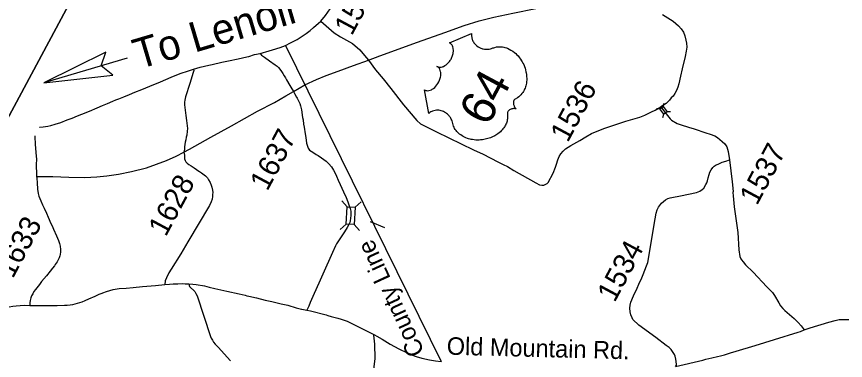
# Model space of a CAD drawing. Extents: x 1376167 to 1379209, y 761324 to 763997.
# Drawn here: x 1376443.7 to 1376608.1, y 762832.7 to 762900.9 of the extents above; entities that cross this region are included whole.
import ezdxf

# ---------------------------------------------------------------- set-up
doc = ezdxf.new("R2010")
doc.units = 0
for name, color, linetype in [('Default', 7, 'Continuous'), ('Old_Level_1', 7, 'Continuous'), ('Prop Terminator CELL', 7, 'Continuous'), ('Sheet Data Field CELL', 7, 'Continuous')]:
    doc.layers.add(name, color=color, linetype=linetype)

msp = doc.modelspace()

# ---------------------------------------------------------------- linework, layer by layer
at = {"layer": 'Default'}
for p, q in [((1376513.48, 762892.25), (1376514.88, 762890.36)), ((1376498.58, 762886.03), (1376500.84, 762887.38)), ((1376571.95, 762883.04), (1376572.15, 762883.71)), ((1376571.32, 762882.57), (1376570.62, 762882.57)), ((1376571.89, 762880.85), (1376572.09, 762881.52)), ((1376573.43, 762882), (1376572.74, 762882.01)), ((1376509.26, 762863.17), (1376508.21, 762864.35)), ((1376510.84, 762863.08), (1376512.01, 762864.13)), ((1376507.88, 762858.67), (1376509.06, 762859.72)), ((1376511.72, 762858.45), (1376510.67, 762859.63))]:
    msp.add_line(p, q, dxfattribs=at)
for points in [[(1376504, 762900), (1376504.98, 762901.08), (1376506.38, 762903.06), (1376507.51, 762904.85), (1376508.46, 762906.38), (1376508.94, 762907.17), (1376511.33, 762910.84), (1376512.6, 762912.83), (1376513.69, 762914.33), (1376514.02, 762914.72), (1376514.69, 762915.33), (1376515.38, 762915.87), (1376516.16, 762916.35), (1376516.96, 762916.71), (1376517.85, 762917.06)], [(1376513.48, 762892.25), (1376515.77, 762893.08), (1376523.24, 762895.79), (1376528.64, 762897.76), (1376532.48, 762899.12), (1376535.43, 762900.03), (1376538.39, 762900.76), (1376542.11, 762901.59), (1376546.68, 762902.48), (1376552.64, 762903.7), (1376557.79, 762904.81), (1376562.66, 762905.79), (1376567.02, 762906.76)], [(1376571.81, 762901.33), (1376573.94, 762899.95), (1376574.48, 762899.55), (1376575, 762899.08), (1376575.55, 762898.44), (1376575.96, 762897.78), (1376576.24, 762897.04), (1376576.46, 762896.2), (1376576.61, 762895.61), (1376576.64, 762894.82), (1376576.55, 762894.05), (1376576.3, 762893), (1376575.72, 762890.5), (1376575.41, 762889.06), (1376575.06, 762887.54), (1376574.86, 762886.87), (1376574.59, 762886.24), (1376574.25, 762885.62), (1376573.93, 762885.13), (1376573.57, 762884.76), (1376573.2, 762884.29), (1376572.53, 762883.68), (1376571.52, 762882.99)], [(1376497, 762895.15), (1376498.02, 762895.67), (1376499.32, 762896.35), (1376500.36, 762896.98), (1376501.15, 762897.55), (1376501.9, 762898.11), (1376502.61, 762898.71), (1376504, 762900)], [(1376504, 762900), (1376506.7, 762897.68), (1376507.96, 762896.88), (1376510.31, 762895.56), (1376511.76, 762894.31)], [(1376491.97, 762893.58), (1376493.78, 762894.08), (1376494.46, 762894.27), (1376495.98, 762894.75), (1376497, 762895.15)], [(1376497.02, 762895.14), (1376527.9, 762832.44)], [(1376511.76, 762894.31), (1376512.68, 762893.17), (1376513.48, 762892.25)], [(1376485.69, 762892.14), (1376487.65, 762892.5), (1376489.38, 762892.9), (1376489.77, 762892.98)], [(1376489.77, 762892.98), (1376490.89, 762893.34), (1376491.97, 762893.58)], [(1376491.97, 762893.58), (1376492.27, 762893.25), (1376492.88, 762892.81), (1376493.84, 762892.09), (1376494.97, 762891.3), (1376495.34, 762891.03), (1376495.61, 762890.79), (1376495.93, 762890.47), (1376496.25, 762890), (1376496.47, 762889.58), (1376496.74, 762889.16), (1376497, 762888.75), (1376497.21, 762888.36), (1376497.86, 762887.23), (1376498.05, 762886.92), (1376498.58, 762886.03)], [(1376478.79, 762890.45), (1376480.09, 762890.84), (1376480.96, 762891.08), (1376481.8, 762891.27), (1376482.46, 762891.41)], [(1376482.46, 762891.41), (1376484.4, 762891.88), (1376485.69, 762892.14)], [(1376500.84, 762887.38), (1376503.2, 762888.44), (1376505.12, 762889.23), (1376507.46, 762890.08), (1376510.52, 762891.2), (1376513.48, 762892.25)], [(1376473.72, 762888.64), (1376474.45, 762888.92), (1376476.32, 762889.64), (1376477.58, 762890.06), (1376478.79, 762890.45)], [(1376478.79, 762890.45), (1376478.81, 762890.21), (1376478.71, 762889.81), (1376478.02, 762887.59), (1376477.19, 762884.95), (1376477.04, 762884.33), (1376476.95, 762883.93), (1376476.95, 762883.41), (1376477.25, 762881.29), (1376477.39, 762880.28), (1376477.55, 762878.67), (1376477.54, 762878.19), (1376477.44, 762877.36), (1376477.33, 762876.94), (1376477.23, 762876.47), (1376477.12, 762876), (1376476.96, 762875.06), (1376476.95, 762874.67), (1376476.95, 762874.43), (1376476.87, 762874)], [(1376514.88, 762890.36), (1376516.37, 762888.57), (1376517.9, 762886.62), (1376520.41, 762883.38)], [(1376470.54, 762887.27), (1376471.75, 762887.78), (1376473.72, 762888.64)], [(1376466.05, 762885.43), (1376467.15, 762885.87), (1376468.53, 762886.45), (1376470.08, 762887.1)], [(1376470.08, 762887.1), (1376470.54, 762887.27)], [(1376459.64, 762882.78), (1376460.74, 762883.24), (1376461.68, 762883.67), (1376462.74, 762884.08), (1376463.37, 762884.35), (1376463.97, 762884.59)], [(1376463.97, 762884.59), (1376464.94, 762884.94), (1376466.05, 762885.43)], [(1376476.87, 762874), (1376477.96, 762874.61), (1376482.21, 762876.94), (1376486.29, 762879.19), (1376491.47, 762882.11), (1376494.84, 762883.82), (1376497.1, 762885.15), (1376498.58, 762886.03)], [(1376498.58, 762886.03), (1376498.83, 762885.63), (1376499.19, 762884.92), (1376499.31, 762884.68), (1376499.84, 762883.64), (1376499.99, 762883.16), (1376500.17, 762882.38), (1376500.41, 762880.9), (1376500.5, 762880.42), (1376500.6, 762879.58), (1376500.73, 762878.94), (1376500.94, 762877.61), (1376501.04, 762876.91), (1376501.19, 762875.81), (1376501.29, 762875.38), (1376501.49, 762874.79), (1376501.76, 762874.42), (1376502.11, 762874.16), (1376502.42, 762873.98), (1376503.13, 762873.56), (1376503.5, 762873.3), (1376504.17, 762872.86), (1376505.12, 762872.19), (1376505.64, 762871.67), (1376506.12, 762871.07), (1376506.53, 762870.42), (1376506.8, 762869.94), (1376507.11, 762869.21), (1376507.5, 762868.45), (1376507.87, 762867.61), (1376508.21, 762866.88), (1376508.56, 762866.13), (1376509.03, 762865.02), (1376509.36, 762864.12), (1376509.64, 762863.33), (1376509.84, 762862.8), (1376509.97, 762862.26), (1376509.99, 762861.95), (1376509.98, 762861.42)], [(1376455.78, 762881.21), (1376456.58, 762881.51), (1376458.11, 762882.15), (1376459.64, 762882.78)], [(1376520.41, 762883.38), (1376523.08, 762880.25), (1376523.84, 762879.62), (1376525.38, 762878.8), (1376526.97, 762878.02), (1376534.32, 762874.47), (1376536.21, 762873.57), (1376539.18, 762872.07), (1376540.2, 762871.53), (1376541.04, 762871.12), (1376542.34, 762870.37), (1376546.7, 762867.9), (1376547.45, 762867.52), (1376547.85, 762867.44), (1376548.25, 762867.47), (1376548.53, 762867.58), (1376548.91, 762867.75), (1376549.13, 762867.96), (1376550.14, 762869.83), (1376550.61, 762871), (1376550.77, 762871.62), (1376551.03, 762872.46), (1376551.33, 762873.14), (1376551.63, 762873.64), (1376552.09, 762874.21), (1376552.56, 762874.65), (1376553.66, 762875.31), (1376555.4, 762876.33), (1376556.62, 762877.06), (1376557.72, 762877.7), (1376560.17, 762878.69), (1376564.57, 762880.13), (1376567.34, 762880.91), (1376568.34, 762881.35), (1376569.62, 762882), (1376570.37, 762882.35), (1376571.52, 762882.99)], [(1376571.52, 762882.99), (1376571.83, 762882.53), (1376573.06, 762880.91), (1376573.35, 762880.59), (1376573.62, 762880.35), (1376574.76, 762879.69), (1376575.53, 762879.42), (1376576.96, 762878.98), (1376578.08, 762878.61), (1376580.45, 762877.82), (1376581.26, 762877.57), (1376582.2, 762877.2), (1376582.73, 762876.89), (1376583.23, 762876.51), (1376583.69, 762876.11), (1376584.16, 762875.62), (1376584.6, 762875.02), (1376584.86, 762874.12), (1376585.11, 762872.44)], [(1376448.21, 762878.95), (1376448.26, 762878.95), (1376448.96, 762879.04), (1376449.87, 762879.18), (1376450.48, 762879.31), (1376451.35, 762879.52), (1376452.46, 762879.89), (1376453.7, 762880.39), (1376454.68, 762880.76), (1376455.78, 762881.21)], [(1376447.27, 762877.2), (1376447.29, 762877.01), (1376447.38, 762875.56), (1376447.5, 762873.93), (1376447.59, 762872.52), (1376447.57, 762871.61), (1376447.57, 762870.78), (1376447.59, 762870.27), (1376447.65, 762869.18)], [(1376447.65, 762869.18), (1376450.89, 762869.14), (1376454.03, 762869.05), (1376457.23, 762868.98), (1376459.62, 762869.07), (1376461.55, 762869.3), (1376463.92, 762869.65), (1376466.49, 762870.13), (1376469.41, 762870.87), (1376473.43, 762872.34), (1376475.35, 762873.18), (1376476.87, 762874)], [(1376476.87, 762874), (1376476.95, 762873.4), (1376476.99, 762872.68), (1376477.11, 762872.37), (1376477.27, 762872.06), (1376477.49, 762871.81), (1376477.86, 762871.53), (1376478.29, 762871.25), (1376478.87, 762870.86), (1376479.82, 762870.23), (1376479.95, 762870.13), (1376480.35, 762869.86), (1376481.14, 762869.3), (1376481.52, 762868.89), (1376481.76, 762868.53), (1376482.09, 762868), (1376482.3, 762867.46), (1376482.42, 762867.05), (1376482.53, 762866.48), (1376482.59, 762865.98), (1376482.57, 762865.59), (1376482.57, 762865.22), (1376482.46, 762864.66), (1376482.29, 762864.13), (1376481.94, 762863.38), (1376477.62, 762856.23), (1376476.23, 762853.85), (1376474.35, 762850.75), (1376473.87, 762850.02), (1376473.39, 762849.09), (1376473.15, 762848.45), (1376473.1, 762847.75)], [(1376567.7, 762849.03), (1376568.02, 762849.74), (1376568.67, 762851.41), (1376568.93, 762852.12), (1376570.07, 762858.78), (1376570.14, 762859.67), (1376570.36, 762860.74), (1376570.54, 762861.9), (1376570.75, 762862.57), (1376571.01, 762863.06), (1376571.21, 762863.35), (1376571.64, 762863.9), (1376572.44, 762864.52), (1376572.88, 762864.77), (1376573.34, 762864.92), (1376573.7, 762865.03), (1376575.41, 762865.35), (1376578.56, 762866), (1376579.21, 762866.28), (1376579.68, 762866.57), (1376580, 762866.86), (1376580.45, 762867.55), (1376580.62, 762867.91), (1376580.76, 762868.31), (1376580.86, 762868.88), (1376581.06, 762869.57), (1376581.19, 762870), (1376581.48, 762870.52), (1376581.8, 762870.92), (1376582, 762871.15), (1376582.06, 762871.24), (1376582.47, 762871.49), (1376582.89, 762871.64), (1376583.69, 762871.99), (1376584.38, 762872.21), (1376585.11, 762872.44)], [(1376585.11, 762872.44), (1376585.64, 762868.12), (1376585.82, 762866.17), (1376585.8, 762866.01), (1376585.85, 762865.33), (1376586.03, 762863.16), (1376586.74, 762858.04), (1376586.98, 762854.59), (1376587.16, 762853.28), (1376587.36, 762852.82), (1376587.49, 762852.63), (1376587.82, 762852.21), (1376588.3, 762851.63), (1376589.78, 762850.19), (1376592.51, 762847.29), (1376592.85, 762846.93), (1376593.64, 762846.16), (1376594.07, 762845.53), (1376594.9, 762844.12), (1376595.23, 762843.5), (1376595.68, 762843), (1376596.09, 762842.58), (1376596.54, 762842.16), (1376597.03, 762841.78), (1376597.94, 762840.98), (1376598.76, 762840.19), (1376599.32, 762839.56), (1376599.9, 762838.75)], [(1376447.65, 762869.18), (1376447.68, 762868.81), (1376447.76, 762867.9), (1376447.82, 762866.68), (1376447.93, 762865.8), (1376448.08, 762865.26), (1376448.46, 762864.31), (1376448.79, 762863.57), (1376449.16, 762862.85), (1376449.58, 762861.86), (1376449.95, 762861.09), (1376450.47, 762859.84), (1376450.71, 762859.35), (1376451.01, 762858.73), (1376451.59, 762857.37), (1376451.97, 762856.49), (1376452.18, 762855.85), (1376452.31, 762855.37), (1376452.37, 762854.71), (1376452.37, 762854.22), (1376452.32, 762853.72), (1376452.25, 762853.42), (1376452.13, 762853), (1376451.69, 762852.22), (1376451.32, 762851.72), (1376451.18, 762851.45), (1376450.81, 762851), (1376450.3, 762850.35), (1376449.57, 762849.44), (1376448.64, 762848.31), (1376448.18, 762847.73), (1376447.44, 762846.77), (1376447.12, 762846.34), (1376446.86, 762845.89), (1376446.64, 762845.48), (1376446.5, 762845.1), (1376446.36, 762844.59), (1376446.29, 762844.07), (1376446.28, 762843.59)], [(1376509.98, 762861.42), (1376509.92, 762860.88), (1376509.86, 762860.35), (1376509.76, 762860.04), (1376509.57, 762859.62), (1376509.28, 762859.06), (1376508.7, 762858.2), (1376508.18, 762857.39), (1376507.91, 762857.01), (1376507.16, 762855.79), (1376506.96, 762855.44), (1376506.36, 762854.07), (1376504.44, 762849.76), (1376503.91, 762848.57), (1376502.47, 762845.34), (1376501.94, 762844.17), (1376501.62, 762843.42), (1376501.38, 762842.94), (1376501.27, 762842.63)], [(1376516.71, 762858.97), (1376513.92, 762860.14)], [(1376574.39, 762831.48), (1376574.57, 762831.71), (1376574.61, 762831.92), (1376574.49, 762832.91), (1376574.36, 762833.5), (1376574.22, 762833.85), (1376573.84, 762834.44), (1376573.53, 762834.81), (1376573.14, 762835.23), (1376572.52, 762835.66), (1376570.5, 762837.21), (1376567.13, 762839.67), (1376565.96, 762840.81), (1376565.78, 762841.11), (1376565.53, 762841.7), (1376565.39, 762842.29), (1376565.36, 762843.02), (1376565.39, 762843.64), (1376565.55, 762844.22), (1376566.09, 762845.52), (1376566.77, 762847.02), (1376567.16, 762847.79), (1376567.7, 762849.03)], [(1376446.28, 762843.59), (1376447.79, 762843.59), (1376449.44, 762843.56), (1376450.57, 762843.54), (1376451.75, 762843.58), (1376453.19, 762843.64), (1376453.73, 762843.63), (1376454.32, 762843.68), (1376454.81, 762843.76), (1376455.32, 762843.87), (1376456.71, 762844.33), (1376457.26, 762844.56), (1376458.01, 762844.89), (1376459.23, 762845.43), (1376459.27, 762845.44), (1376460.03, 762845.79), (1376460.65, 762846.02), (1376460.77, 762846.07), (1376461.5, 762846.38), (1376462.82, 762846.73)], [(1376462.82, 762846.73), (1376464.02, 762846.92), (1376465.42, 762846.98), (1376466.83, 762847.14), (1376468.66, 762847.32), (1376471.25, 762847.57), (1376473.1, 762847.75)], [(1376473.1, 762847.75), (1376474, 762847.83), (1376474.76, 762847.89), (1376475.65, 762847.9), (1376476.55, 762847.93), (1376477.13, 762847.9), (1376477.87, 762847.88)], [(1376477.87, 762847.88), (1376477.92, 762847.53), (1376477.99, 762847.36), (1376478.14, 762847.15), (1376478.83, 762846.55), (1376479.02, 762846.34), (1376479.26, 762845.98), (1376479.49, 762845.47), (1376482.12, 762837.43), (1376482.28, 762837.07), (1376482.52, 762836.68), (1376482.76, 762836.32), (1376483.08, 762835.92), (1376483.67, 762835.3), (1376486.09, 762832.57)], [(1376477.87, 762847.88), (1376478.62, 762847.81), (1376479.32, 762847.72), (1376480.92, 762847.48), (1376481.88, 762847.24), (1376483.03, 762846.92), (1376485.36, 762846.43), (1376487.81, 762845.89), (1376489, 762845.59), (1376489.36, 762845.49), (1376489.74, 762845.39), (1376491.25, 762845.06), (1376493.01, 762844.63), (1376494.32, 762844.37), (1376496.18, 762843.92), (1376497.47, 762843.61), (1376499.11, 762843.13), (1376500.22, 762842.85), (1376500.28, 762842.83), (1376501.27, 762842.63)], [(1376428.65, 762842.47), (1376429.73, 762842.51), (1376431.08, 762842.55), (1376432.73, 762842.67), (1376433.63, 762842.64), (1376436.24, 762842.87), (1376437.65, 762842.9), (1376439.73, 762842.96), (1376441.45, 762843.2), (1376442.95, 762843.46), (1376443.59, 762843.53), (1376444.38, 762843.56), (1376445.29, 762843.61), (1376446.28, 762843.59)], [(1376501.27, 762842.63), (1376502.01, 762842.48), (1376505.08, 762841.7), (1376505.4, 762841.61), (1376506.08, 762841.41), (1376507.4, 762841.05), (1376508.05, 762840.87), (1376508.65, 762840.67), (1376509.25, 762840.46), (1376510.47, 762839.87), (1376512.2, 762839), (1376513.64, 762838.25), (1376514.65, 762837.73)], [(1376599.9, 762838.75), (1376601.09, 762839.11), (1376604.8, 762840.25), (1376606.05, 762840.61), (1376606.9, 762840.79), (1376607.53, 762840.82), (1376608.79, 762840.77)], [(1376574.39, 762831.48), (1376579.85, 762832.75), (1376580.41, 762832.9), (1376581.64, 762833.17), (1376582.76, 762833.45), (1376583.31, 762833.6), (1376584.11, 762833.81), (1376585.32, 762834.18), (1376586.42, 762834.49), (1376590.21, 762835.65), (1376594.03, 762836.84), (1376598.72, 762838.28), (1376599.2, 762838.44), (1376599.9, 762838.75)], [(1376514.5, 762837.69), (1376514.66, 762835.92), (1376514.73, 762833.03), (1376514.55, 762831.4), (1376514.4, 762829.63), (1376514.26, 762826.49), (1376514.63, 762822.34)], [(1376514.65, 762837.73), (1376515.16, 762837.46), (1376516.17, 762836.91), (1376517.77, 762835.88), (1376519.52, 762834.96), (1376520.06, 762834.7), (1376521.21, 762834.17), (1376522.02, 762833.77), (1376522.95, 762833.46), (1376524.07, 762833.11)], [(1376524.07, 762833.11), (1376525.61, 762832.77), (1376526.77, 762832.56), (1376527.9, 762832.44)]]:
    msp.add_lwpolyline(points, dxfattribs=at)
for points in [[(1376524.58, 762886.33), (1376524.72, 762886.27), (1376524.89, 762886.22), (1376524.99, 762886.2), (1376525.19, 762886.19), (1376525.44, 762886.21), (1376525.72, 762886.28), (1376525.98, 762886.39), (1376526.14, 762886.48), (1376526.38, 762886.64), (1376526.62, 762886.83), (1376526.85, 762887.07), (1376527.06, 762887.33), (1376527.27, 762887.62), (1376527.44, 762887.93), (1376527.59, 762888.28), (1376527.72, 762888.69), (1376527.77, 762888.89), (1376527.81, 762889.11), (1376527.83, 762889.33), (1376527.83, 762889.58), (1376527.81, 762889.79), (1376527.79, 762889.96), (1376527.71, 762890.22), (1376527.62, 762890.45), (1376527.55, 762890.56), (1376527.49, 762890.66), (1376527.33, 762890.84), (1376527.25, 762890.9), (1376527.08, 762891.01), (1376527.23, 762890.94), (1376527.34, 762890.91), (1376527.44, 762890.88), (1376527.56, 762890.87), (1376527.74, 762890.86), (1376527.89, 762890.88), (1376528.14, 762890.93), (1376528.28, 762890.98), (1376528.39, 762891.02), (1376528.66, 762891.16), (1376528.93, 762891.35), (1376529.06, 762891.45), (1376529.17, 762891.56), (1376529.31, 762891.7), (1376529.44, 762891.84), (1376529.56, 762892), (1376529.68, 762892.16), (1376529.79, 762892.33), (1376529.87, 762892.47), (1376529.97, 762892.65), (1376530.04, 762892.82), (1376530.12, 762893), (1376530.18, 762893.2), (1376530.23, 762893.37), (1376530.28, 762893.59), (1376530.32, 762893.8), (1376530.33, 762893.99), (1376530.33, 762894.25), (1376530.32, 762894.47), (1376530.29, 762894.64), (1376530.23, 762894.86), (1376530.15, 762895.08), (1376530.08, 762895.22), (1376529.99, 762895.34), (1376529.89, 762895.45), (1376529.78, 762895.56), (1376529.67, 762895.63), (1376529.58, 762895.69), (1376533.93, 762897.56), (1376533.92, 762897.47), (1376533.91, 762897.24), (1376533.92, 762897.06), (1376533.96, 762896.75), (1376533.99, 762896.6), (1376534.03, 762896.46), (1376534.08, 762896.32), (1376534.13, 762896.19), (1376534.21, 762896.03), (1376534.3, 762895.87), (1376534.4, 762895.71), (1376534.49, 762895.58), (1376534.7, 762895.34), (1376534.84, 762895.21), (1376534.96, 762895.1), (1376535.23, 762894.9), (1376535.37, 762894.82), (1376535.5, 762894.75), (1376535.65, 762894.68), (1376535.8, 762894.62), (1376535.96, 762894.56), (1376536.1, 762894.52), (1376536.27, 762894.47), (1376536.49, 762894.44), (1376536.7, 762894.41), (1376537.06, 762894.41), (1376537.46, 762894.45), (1376537.69, 762894.5), (1376537.9, 762894.56), (1376538.18, 762894.67), (1376538.34, 762894.72), (1376538.53, 762894.78), (1376538.88, 762894.86), (1376539.03, 762894.88), (1376539.2, 762894.9), (1376539.37, 762894.91), (1376539.56, 762894.91), (1376539.71, 762894.91), (1376540.05, 762894.87), (1376540.37, 762894.81), (1376540.53, 762894.77), (1376540.88, 762894.66), (1376541.06, 762894.6), (1376541.38, 762894.46), (1376541.76, 762894.25), (1376542.1, 762894.03), (1376542.49, 762893.74), (1376542.71, 762893.55), (1376542.95, 762893.31), (1376543.16, 762893.09), (1376543.45, 762892.74), (1376543.65, 762892.46), (1376543.88, 762892.12), (1376544.01, 762891.9), (1376544.14, 762891.66), (1376544.28, 762891.36), (1376544.42, 762891.02), (1376544.56, 762890.64), (1376544.65, 762890.34), (1376544.74, 762889.96), (1376544.79, 762889.74), (1376544.83, 762889.43), (1376544.87, 762889.02), (1376544.89, 762888.63), (1376544.88, 762888.31), (1376544.86, 762888.04), (1376544.81, 762887.69), (1376544.68, 762887.13), (1376544.63, 762886.94), (1376544.55, 762886.71), (1376544.46, 762886.51), (1376544.37, 762886.31), (1376544.24, 762886.06), (1376544.08, 762885.82), (1376543.92, 762885.6), (1376543.73, 762885.37), (1376543.51, 762885.16), (1376543.3, 762884.97), (1376543.05, 762884.79), (1376542.58, 762884.53), (1376542.45, 762884.44), (1376542.4, 762884.39), (1376542.31, 762884.23), (1376542.26, 762884.07), (1376542.24, 762883.89), (1376542.24, 762883.77), (1376542.26, 762883.61), (1376542.28, 762883.48), (1376542.33, 762883.31), (1376542.37, 762883.18), (1376542.41, 762883.09), (1376542.53, 762882.88), (1376542.59, 762882.79), (1376542.68, 762882.69), (1376542.82, 762882.56), (1376542.59, 762882.62), (1376542.42, 762882.64), (1376542.27, 762882.63), (1376542.13, 762882.61), (1376541.94, 762882.57), (1376541.78, 762882.52), (1376541.62, 762882.45), (1376541.47, 762882.36), (1376541.36, 762882.28), (1376541.27, 762882.21), (1376541.18, 762882.1), (1376541.12, 762882.01), (1376541.08, 762881.93), (1376541.04, 762881.81), (1376541.07, 762881.6), (1376541.09, 762881.41), (1376541.1, 762881.21), (1376541.1, 762880.98), (1376541.09, 762880.81), (1376541.07, 762880.62), (1376541.03, 762880.4), (1376540.98, 762880.17), (1376540.91, 762879.94), (1376540.84, 762879.75), (1376540.75, 762879.54), (1376540.66, 762879.36), (1376540.56, 762879.18), (1376540.46, 762879.02), (1376540.33, 762878.83), (1376540.16, 762878.6), (1376540.01, 762878.42), (1376539.84, 762878.24), (1376539.65, 762878.05), (1376539.43, 762877.86), (1376539.14, 762877.64), (1376538.92, 762877.49), (1376538.56, 762877.26), (1376538.09, 762877.02), (1376537.7, 762876.86), (1376537.4, 762876.75), (1376536.92, 762876.61), (1376536.61, 762876.54), (1376536.09, 762876.45), (1376535.72, 762876.41), (1376535.46, 762876.4), (1376535.05, 762876.39), (1376534.8, 762876.4), (1376534.45, 762876.43), (1376534.13, 762876.48), (1376533.83, 762876.53), (1376533.65, 762876.57), (1376533.34, 762876.66), (1376533.12, 762876.73), (1376532.83, 762876.84), (1376532.53, 762876.98), (1376532.26, 762877.11), (1376532.05, 762877.24), (1376531.8, 762877.4), (1376531.55, 762877.59), (1376531.35, 762877.77), (1376531.21, 762877.9), (1376531.04, 762878.08), (1376530.86, 762878.3), (1376530.7, 762878.52), (1376530.58, 762878.72), (1376530.46, 762878.95), (1376530.36, 762879.17), (1376530.27, 762879.43), (1376530.19, 762879.69), (1376530.15, 762879.92), (1376530.07, 762880.21), (1376530.01, 762880.37), (1376529.91, 762880.57), (1376529.82, 762880.74), (1376529.73, 762880.89), (1376529.59, 762881.09), (1376529.48, 762881.23), (1376529.3, 762881.42), (1376529.17, 762881.54), (1376528.99, 762881.69), (1376528.82, 762881.81), (1376528.59, 762881.95), (1376528.39, 762882.04), (1376528.15, 762882.14), (1376527.91, 762882.21), (1376527.7, 762882.26), (1376527.44, 762882.3), (1376527.24, 762882.31), (1376526.96, 762882.3), (1376526.69, 762882.27), (1376526.45, 762882.21), (1376526.22, 762882.14), (1376526.04, 762882.06), (1376525.88, 762881.98), (1376525.69, 762881.87), (1376525.52, 762881.75), (1376525.43, 762881.67)], [(1376572.09, 762881.52), (1376571.31, 762882.56), (1376571.96, 762883.05), (1376572.74, 762882.01)], [(1376509.06, 762859.72), (1376509.25, 762863.17), (1376510.87, 762863.08), (1376510.67, 762859.63)]]:
    msp.add_lwpolyline(points, close=True, dxfattribs=at)
at = {"layer": 'Old_Level_1'}
for points in [[(1376622.61, 762553.05), (1376345.79, 762701.47), (1376550.88, 763083.99), (1376827.7, 762935.57)], [(1376345.79, 762701.47), (1376660.36, 762532.81), (1376865.45, 762915.33), (1376550.88, 763083.99)]]:
    msp.add_lwpolyline(points, close=True, dxfattribs=at)
at = {"layer": 'Prop Terminator CELL'}
msp.add_lwpolyline([(1376461.37, 762893.81), (1376449.08, 762887.74), (1376462.78, 762889.3), (1376460.45, 762891.11)], close=True, dxfattribs=at)
at = {"layer": 'Sheet Data Field CELL'}
msp.add_line((1376465.61, 762892.65), (1376449.08, 762887.74), dxfattribs=at)

# ---------------------------------------------------------------- texts
at = {"layer": 'Default'}
for s, height, rotation, p in [('To Lenoir', 6, 16.5293, (1376467.85, 762890.4)), ('64', 6.801, 61.8015, (1376537.16, 762878.91))]:
    msp.add_text(s, height=height, rotation=rotation, dxfattribs=at).set_placement(p)
at = {"layer": 'Old_Level_1'}
for s, height, rotation, p in [('1536', 4.185, 61.8015, (1376510.17, 762896.94)), ('1536', 4.185, 61.8015, (1376553.02, 762875.74)), ('1637', 4.185, 61.8015, (1376493.41, 762866.1)), ('1537', 4.185, 61.8015, (1376590.56, 762863.26)), ('1628', 4.185, 61.8015, (1376473.27, 762857.06)), ('1633', 4.185, 61.8015, (1376442.92, 762848.77)), ('County Line', 3.4876, 114.6834, (1376524.67, 762834.35)), ('1534', 4.185, 61.8015, (1376562.32, 762844.01)), ('Old Mountain Rd.', 3.4876, 358.5389, (1376528.98, 762833.82))]:
    msp.add_text(s, height=height, rotation=rotation, dxfattribs=at).set_placement(p)

doc.saveas('drawing.dxf')
